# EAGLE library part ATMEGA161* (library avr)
MICROCONTROLLER 16 Kbytes FLASH, 512 bytes EEPROM 1 Kbytes SRAM dual UART hardware multiplier
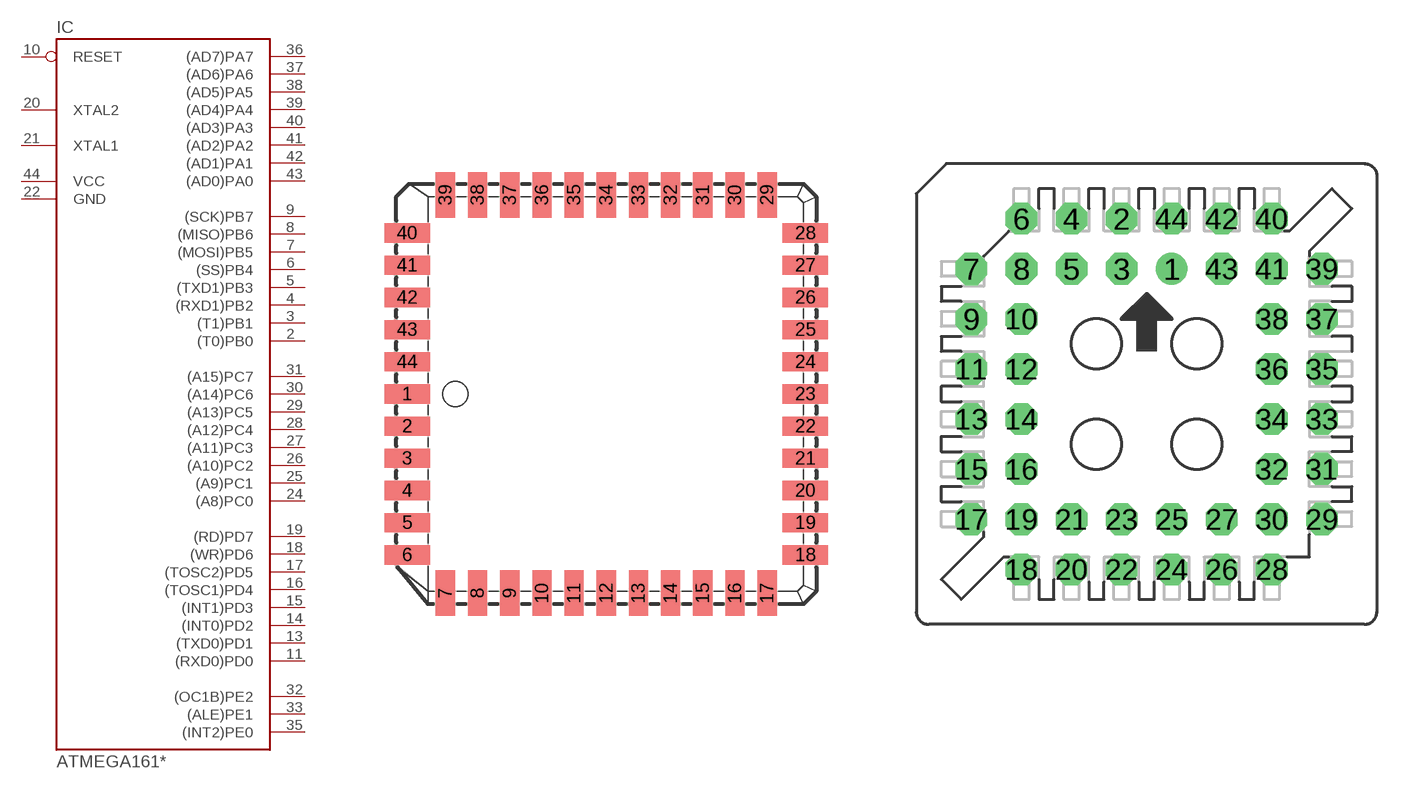
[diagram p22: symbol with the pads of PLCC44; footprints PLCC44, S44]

Designator prefix IC

## ATMEGA161-8J, ATMEGA161L-4J  [PLCC44]
1  NC1  nc
2  (T0)PB0
3  (T1)PB1
4  (RXD1)PB2
5  (TXD1)PB3
6  (SS)PB4
7  (MOSI)PB5
8  (MISO)PB6
9  (SCK)PB7
10  RESET  in
11  (RXD0)PD0
12  NC2  nc
13  (TXD0)PD1
14  (INT0)PD2
15  (INT1)PD3
16  (TOSC1)PD4
17  (TOSC2)PD5
18  (WR)PD6
19  (RD)PD7
20  XTAL2  in
21  XTAL1  in
22  GND  pwr
23  NC3  nc
24  (A8)PC0
25  (A9)PC1
26  (A10)PC2
27  (A11)PC3
28  (A12)PC4
29  (A13)PC5
30  (A14)PC6
31  (A15)PC7
32  (OC1B)PE2
33  (ALE)PE1
34  NC4  nc
35  (INT2)PE0
36  (AD7)PA7
37  (AD6)PA6
38  (AD5)PA5
39  (AD4)PA4
40  (AD3)PA3
41  (AD2)PA2
42  (AD1)PA1
43  (AD0)PA0
44  VCC  pwr

## ATMEGA161-8J-S, ATMEGA161L-4J-S  [S44]
Pads as for PLCC44

## ATMEGA161-8J-SM, ATMEGA161L-4J-SM  [PLCC-SM44]
Pads as for PLCC44

## ATMEGA161-8A, ATMEGA161L-4A  [TQFP44]
1  (MOSI)PB5
2  (MISO)PB6
3  (SCK)PB7
4  RESET  in
5  (RXD0)PD0
6  NC1  nc
7  (TXD0)PD1
8  (INT0)PD2
9  (INT1)PD3
10  (TOSC1)PD4
11  (TOSC2)PD5
12  (WR)PD6
13  (RD)PD7
14  XTAL2  in
15  XTAL1  in
16  GND  pwr
17  NC2  nc
18  (A8)PC0
19  (A9)PC1
20  (A10)PC2
21  (A11)PC3
22  (A12)PC4
23  (A13)PC5
24  (A14)PC6
25  (A15)PC7
26  (OC1B)PE2
27  (ALE)PE1
28  NC3  nc
29  (INT2)PE0
30  (AD7)PA7
31  (AD6)PA6
32  (AD5)PA5
33  (AD4)PA4
34  (AD3)PA3
35  (AD2)PA2
36  (AD1)PA1
37  (AD0)PA0
38  VCC  pwr
39  NC4  nc
40  (T0)PB0
41  (T1)PB1
42  (RXD1)PB2
43  (TXD1)PB3
44  (SS)PB4

## Footprint PLCC44 (pad centres in mm)
Plastic J-Leaded Chip Carrier
smd 1.8 x 0.76: 1 -7.86,0; 2 -7.86,-1.27; 3 -7.86,-2.54; 4 -7.86,-3.81; 5 -7.86,-5.08; 6 -7.86,-6.35; 18 7.86,-6.35; 19 7.86,-5.08; 20 7.86,-3.81; 21 7.86,-2.54; 22 7.86,-1.27; 23 7.86,0; 24 7.86,1.27; 25 7.86,2.54; 26 7.86,3.81; 27 7.86,5.08; 28 7.86,6.35; 40 -7.86,6.35; 41 -7.86,5.08; 42 -7.86,3.81; 43 -7.86,2.54; 44 -7.86,1.27
smd 0.76 x 1.8: 7 -6.35,-7.86; 8 -5.08,-7.86; 9 -3.81,-7.86; 10 -2.54,-7.86; 11 -1.27,-7.86; 12 0,-7.86; 13 1.27,-7.86; 14 2.54,-7.86; 15 3.81,-7.86; 16 5.08,-7.86; 17 6.35,-7.86; 29 6.35,7.86; 30 5.08,7.86; 31 3.81,7.86; 32 2.54,7.86; 33 1.27,7.86; 34 0,7.86; 35 -1.27,7.86; 36 -2.54,7.86; 37 -3.81,7.86; 38 -5.08,7.86; 39 -6.35,7.86

## Footprint S44 (pad centres in mm)
Throughhole Plastic J-Leaded Chip Carrier Socket
drill 0.813 pad 1.6 round: 1 1.27,6.35
drill 0.813 pad 1.6 octagon: 2 -1.27,8.89; 3 -1.27,6.35; 4 -3.81,8.89; 5 -3.81,6.35; 6 -6.35,8.89; 7 -8.89,6.35; 8 -6.35,6.35; 9 -8.89,3.81; 10 -6.35,3.81; 11 -8.89,1.27; 12 -6.35,1.27; 13 -8.89,-1.27; 14 -6.35,-1.27; 15 -8.89,-3.81; 16 -6.35,-3.81; 17 -8.89,-6.35; 18 -6.35,-8.89; 19 -6.35,-6.35; 20 -3.81,-8.89; 21 -3.81,-6.35; 22 -1.27,-8.89; 23 -1.27,-6.35; 24 1.27,-8.89; 25 1.27,-6.35; 26 3.81,-8.89; 27 3.81,-6.35; 28 6.35,-8.89; 29 8.89,-6.35; 30 6.35,-6.35; 31 8.89,-3.81; 32 6.35,-3.81; 33 8.89,-1.27; 34 6.35,-1.27; 35 8.89,1.27; 36 6.35,1.27; 37 8.89,3.81; 38 6.35,3.81; 39 8.89,6.35; 40 6.35,8.89; 41 6.35,6.35; 42 3.81,8.89; 43 3.81,6.35; 44 1.27,8.89

## Footprint PLCC-SM44 (pad centres in mm)
SMD Plastic J-Leaded Chip Carrier Socket
smd 2.591 x 0.66: 1 -8.89,0; 2 -8.89,-1.27; 3 -8.89,-2.54; 4 -8.89,-3.81; 5 -8.89,-5.08; 6 -8.89,-6.35; 18 8.89,-6.35; 19 8.89,-5.08; 20 8.89,-3.81; 21 8.89,-2.54; 22 8.89,-1.27; 23 8.89,0; 24 8.89,1.27; 25 8.89,2.54; 26 8.89,3.81; 27 8.89,5.08; 28 8.89,6.35; 40 -8.89,6.35; 41 -8.89,5.08; 42 -8.89,3.81; 43 -8.89,2.54; 44 -8.89,1.27
smd 0.66 x 2.591: 7 -6.35,-8.89; 8 -5.08,-8.89; 9 -3.81,-8.89; 10 -2.54,-8.89; 11 -1.27,-8.89; 12 0,-8.89; 13 1.27,-8.89; 14 2.54,-8.89; 15 3.81,-8.89; 16 5.08,-8.89; 17 6.35,-8.89; 29 6.35,8.89; 30 5.08,8.89; 31 3.81,8.89; 32 2.54,8.89; 33 1.27,8.89; 34 0,9.017; 35 -1.27,8.89; 36 -2.54,8.89; 37 -3.81,8.89; 38 -5.08,8.89; 39 -6.35,8.89

## Footprint TQFP44 (pad centres in mm)
Thin Plasic Quad Flat Package
smd 1.5 x 0.5: 1 -5.8,4; 2 -5.8,3.2; 3 -5.8,2.4; 4 -5.8,1.6; 5 -5.8,0.8; 6 -5.8,0; 7 -5.8,-0.8; 8 -5.8,-1.6; 9 -5.8,-2.4; 10 -5.8,-3.2; 11 -5.8,-4; 23 5.8,-4; 24 5.8,-3.2; 25 5.8,-2.4; 26 5.8,-1.6; 27 5.8,-0.8; 28 5.8,0; 29 5.8,0.8; 30 5.8,1.6; 31 5.8,2.4; 32 5.8,3.2; 33 5.8,4
smd 0.5 x 1.5: 12 -4,-5.8; 13 -3.2,-5.8; 14 -2.4,-5.8; 15 -1.6,-5.8; 16 -0.8,-5.8; 17 0,-5.8; 18 0.8,-5.8; 19 1.6,-5.8; 20 2.4,-5.8; 21 3.2,-5.8; 22 4,-5.8; 34 4,5.8; 35 3.2,5.8; 36 2.4,5.8; 37 1.6,5.8; 38 0.8,5.8; 39 0,5.8; 40 -0.8,5.8; 41 -1.6,5.8; 42 -2.4,5.8; 43 -3.2,5.8; 44 -4,5.8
